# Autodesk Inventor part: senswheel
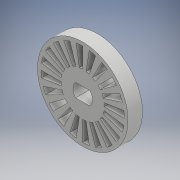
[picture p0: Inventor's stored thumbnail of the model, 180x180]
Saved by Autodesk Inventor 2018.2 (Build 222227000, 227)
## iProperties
Created: 2018-05
Part Number: senswheel
Material: Типовые
Document SubType Name: Modeling
Designer: AbstractCat
Density: 1 g/cm^3
Appearance: По умолчанию
Author: AbstractCat
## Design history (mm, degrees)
sketch "Эскиз1"
  geometry: L1 (-1.967, 1.85)-(1.967, 1.85); L2 (1.967, -1.85)-(-1.967, -1.85); L3 (11.5, 0)-(6, 0); L4 (11.358, 1.799)-(5.926, 0.939); L5 (10.937, 3.554)-(5.706, 1.854); L6 (10.247, 5.221)-(5.346, 2.724); L7 (9.304, 6.76)-(4.854, 3.527); L8 (8.132, 8.132)-(4.243, 4.243); L9 (6.76, 9.304)-(3.527, 4.854); L10 (5.221, 10.247)-(2.724, 5.346); L11 (3.554, 10.937)-(1.854, 5.706); L12 (1.799, 11.358)-(0.939, 5.926); L13 (0, 11.5)-(0, 6); L14 (-1.799, 11.358)-(-0.939, 5.926); L15 (-3.554, 10.937)-(-1.854, 5.706); L16 (-5.221, 10.247)-(-2.724, 5.346); L17 (-6.76, 9.304)-(-3.527, 4.854); L18 (-8.132, 8.132)-(-4.243, 4.243); L19 (-9.304, 6.76)-(-4.854, 3.527); L20 (-10.247, 5.221)-(-5.346, 2.724); L21 (-10.937, 3.554)-(-5.706, 1.854); L22 (-11.358, 1.799)-(-5.926, 0.939); L23 (-11.5, 0)-(-6, 0); L24 (-11.358, -1.799)-(-5.926, -0.939); L25 (-10.937, -3.554)-(-5.706, -1.854); L26 (-10.247, -5.221)-(-5.346, -2.724); L27 (-9.304, -6.76)-(-4.854, -3.527); L28 (-8.132, -8.132)-(-4.243, -4.243); L29 (-6.76, -9.304)-(-3.527, -4.854); L30 (-5.221, -10.247)-(-2.724, -5.346); L31 (-3.554, -10.937)-(-1.854, -5.706); L32 (-1.799, -11.358)-(-0.939, -5.926); L33 (0, -11.5)-(0, -6); L34 (1.799, -11.358)-(0.939, -5.926); L35 (3.554, -10.937)-(1.854, -5.706); L36 (5.221, -10.247)-(2.724, -5.346); L37 (6.76, -9.304)-(3.527, -4.854); L38 (8.132, -8.132)-(4.243, -4.243); L39 (9.304, -6.76)-(4.854, -3.527); L40 (10.247, -5.221)-(5.346, -2.724); L41 (10.937, -3.554)-(5.706, -1.854); L42 (11.358, -1.799)-(5.926, -0.939); C1 r 12.5 at (0, 0); A1 r 2.7 centre (0, 0) between (1.967, -1.85) and (1.967, 1.85); A2 r 2.7 centre (0, 0) between (-1.967, 1.85) and (-1.967, -1.85); A3 r 11.5 centre (0, 0) between (11.358, 1.799) and (10.937, 3.554); A4 r 6 centre (0, 0) between (5.926, 0.939) and (5.706, 1.854); A5 r 6 centre (0, 0) between (5.926, -0.939) and (6, 0); A6 r 6 centre (0, 0) between (5.346, -2.724) and (5.706, -1.854); A7 r 6 centre (0, 0) between (4.243, -4.243) and (4.854, -3.527); A8 r 6 centre (0, 0) between (2.724, -5.346) and (3.527, -4.854); A9 r 6 centre (0, 0) between (0.939, -5.926) and (1.854, -5.706); A10 r 6 centre (0, 0) between (-0.939, -5.926) and (0, -6); A11 r 6 centre (0, 0) between (-2.724, -5.346) and (-1.854, -5.706); A12 r 6 centre (0, 0) between (-4.243, -4.243) and (-3.527, -4.854); A13 r 6 centre (0, 0) between (-5.346, -2.724) and (-4.854, -3.527); A14 r 6 centre (0, 0) between (-5.926, -0.939) and (-5.706, -1.854); A15 r 6 centre (0, 0) between (-5.926, 0.939) and (-6, 0); A16 r 6 centre (0, 0) between (-5.346, 2.724) and (-5.706, 1.854); A17 r 6 centre (0, 0) between (-4.243, 4.243) and (-4.854, 3.527); A18 r 6 centre (0, 0) between (-2.724, 5.346) and (-3.527, 4.854); A19 r 6 centre (0, 0) between (-0.939, 5.926) and (-1.854, 5.706); A20 r 6 centre (0, 0) between (0.939, 5.926) and (0, 6); A21 r 6 centre (0, 0) between (2.724, 5.346) and (1.854, 5.706); A22 r 6 centre (0, 0) between (5.346, 2.724) and (4.854, 3.527); A23 r 6 centre (0, 0) between (4.243, 4.243) and (3.527, 4.854); A24 r 11.5 centre (0, 0) between (10.247, 5.221) and (9.304, 6.76); A25 r 11.5 centre (0, 0) between (8.132, 8.132) and (6.76, 9.304); A26 r 11.5 centre (0, 0) between (5.221, 10.247) and (3.554, 10.937); A27 r 11.5 centre (0, 0) between (1.799, 11.358) and (0, 11.5); A28 r 11.5 centre (0, 0) between (-1.799, 11.358) and (-3.554, 10.937); A29 r 11.5 centre (0, 0) between (-5.221, 10.247) and (-6.76, 9.304); A30 r 11.5 centre (0, 0) between (-8.132, 8.132) and (-9.304, 6.76); A31 r 11.5 centre (0, 0) between (-10.247, 5.221) and (-10.937, 3.554); A32 r 11.5 centre (0, 0) between (-11.358, 1.799) and (-11.5, 0); A33 r 11.5 centre (0, 0) between (-11.358, -1.799) and (-10.937, -3.554); A34 r 11.5 centre (0, 0) between (-10.247, -5.221) and (-9.304, -6.76); A35 r 11.5 centre (0, 0) between (-8.132, -8.132) and (-6.76, -9.304); A36 r 11.5 centre (0, 0) between (-5.221, -10.247) and (-3.554, -10.937); A37 r 11.5 centre (0, 0) between (-1.799, -11.358) and (0, -11.5); A38 r 11.5 centre (0, 0) between (1.799, -11.358) and (3.554, -10.937); A39 r 11.5 centre (0, 0) between (5.221, -10.247) and (6.76, -9.304); A40 r 11.5 centre (0, 0) between (8.132, -8.132) and (9.304, -6.76); A41 r 11.5 centre (0, 0) between (10.247, -5.221) and (10.937, -3.554); A42 r 11.5 centre (0, 0) between (11.358, -1.799) and (11.5, 0); 1 further point
  constraints: 84 end point, 84 point on circle, 43 centre point, 4 coincident, 2 horizontal, 1 parallel, 121 other
  dimensions: "d7" = 360 deg dimension on point (0, 0) L3.start (derived)
extrude "Выдавливание1" new body sketch "Эскиз1" distance "d9" = 4; taper "d10" = 0 deg
node "Твердое тело1"
other parameters: "d2" = 5.4
